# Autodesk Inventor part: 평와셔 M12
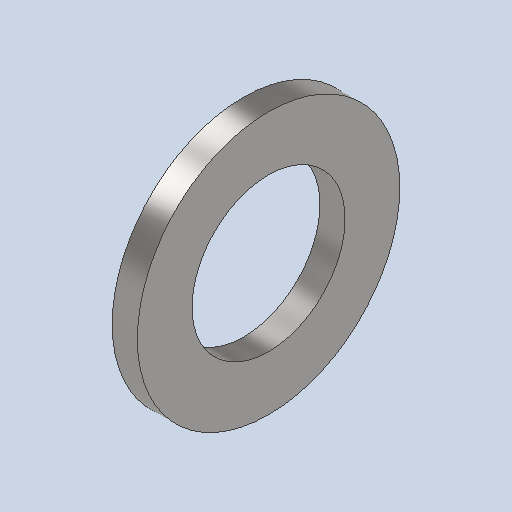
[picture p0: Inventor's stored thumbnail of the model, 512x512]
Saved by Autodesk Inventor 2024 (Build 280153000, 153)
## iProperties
Created: 2024-07
Part Number: 평와셔 M12
Material: 강철, 연강
Description: 평면 와셔
Document SubType Name: Modeling
Designer: com
Density: 7.85 g/cm^3
Appearance: 기본값
Author: jhkim
Sending System: Autodesk Inventor 2025
Preprocessor: ST-DEVELOPER v20
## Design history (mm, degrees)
feature "Solid1"
node "솔리드1"
